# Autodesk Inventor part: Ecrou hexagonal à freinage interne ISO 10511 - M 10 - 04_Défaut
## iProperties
Shininess: 64.0
Length Units: 11269
Angle Units: 11279
Time Units: 11290
Mass Units: 11283
Length Display Precision: 3
Angle Display Precision: 2
Compacted: True
Part Number: Ecrou hexagonal à freinage interne ISO 10511 - M 10 - 04_Défaut
Document SubType Name: Modeling
Created: 2006-01
Material: Par défaut
Designer: riri
Density: 0.0
Volumn: 0.0
Area: 0.0
PropertySet Name: Model Information
Control State: 0
Master: False
Checked Out: False
Author: riri
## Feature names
1. Base1
